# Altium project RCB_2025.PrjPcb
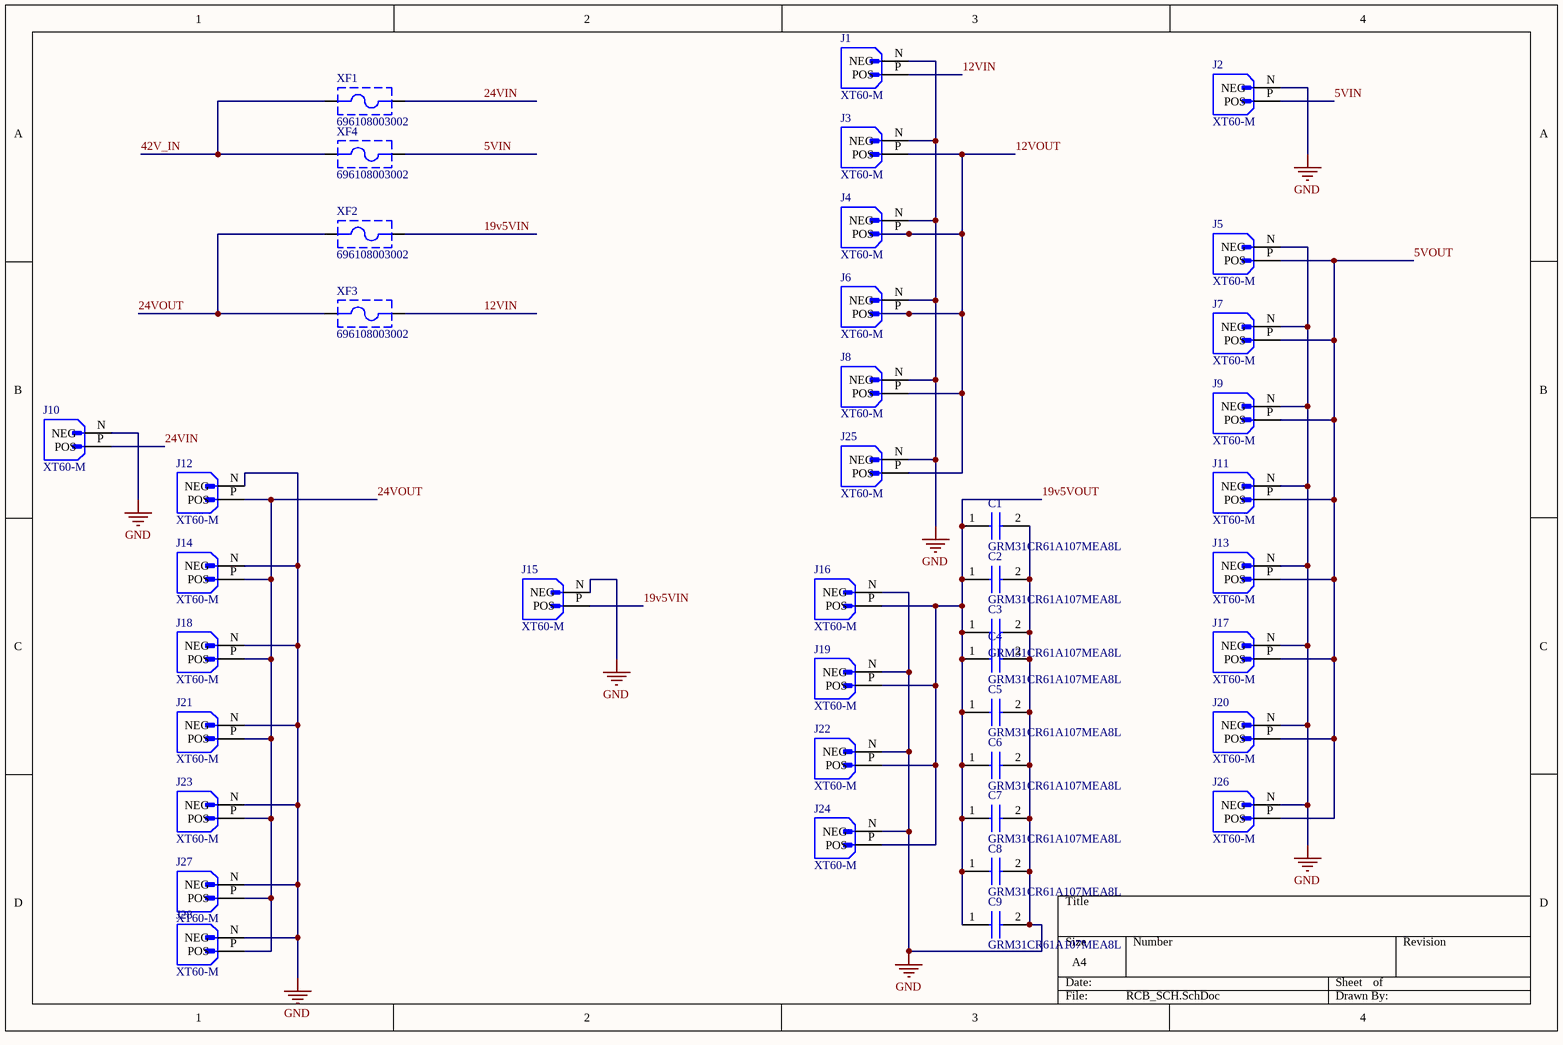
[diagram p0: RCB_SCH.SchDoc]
1 sheet, 41 parts. Net scope: global (net labels, ports and power ports of the same name join across sheets).
Board file: RCB_PCB.PcbDoc

## Sheet RCB_SCH.SchDoc
size A4; SheetNumber: 1; SheetTotal: 1

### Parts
C1  GRM31CR61A107MEA8L  [GRM31x]
C2  GRM31CR61A107MEA8L  [GRM31x]
C3  GRM31CR61A107MEA8L  [GRM31x]
C4  GRM31CR61A107MEA8L  [GRM31x]
C5  GRM31CR61A107MEA8L  [GRM31x]
C6  GRM31CR61A107MEA8L  [GRM31x]
C7  GRM31CR61A107MEA8L  [GRM31x]
C8  GRM31CR61A107MEA8L  [GRM31x]
C9  GRM31CR61A107MEA8L  [GRM31x]
J1  XT60-M  [XT60-M-Footprint-1]
J2  XT60-M  [XT60-M-Footprint-1]
J3  XT60-M  [XT60-M-Footprint-1]
J4  XT60-M  [XT60-M-Footprint-1]
J5  XT60-M  [XT60-M-Footprint-1]
J6  XT60-M  [XT60-M-Footprint-1]
J7  XT60-M  [XT60-M-Footprint-1]
J8  XT60-M  [XT60-M-Footprint-1]
J9  XT60-M  [XT60-M-Footprint-1]
J10  XT60-M  [XT60-M-Footprint-1]
J11  XT60-M  [XT60-M-Footprint-1]
J12  XT60-M  [XT60-M-Footprint-1]
J13  XT60-M  [XT60-M-Footprint-1]
J14  XT60-M  [XT60-M-Footprint-1]
J15  XT60-M  [XT60-M-Footprint-1]
J16  XT60-M  [XT60-M-Footprint-1]
J17  XT60-M  [XT60-M-Footprint-1]
J18  XT60-M  [XT60-M-Footprint-1]
J19  XT60-M  [XT60-M-Footprint-1]
J20  XT60-M  [XT60-M-Footprint-1]
J21  XT60-M  [XT60-M-Footprint-1]
J22  XT60-M  [XT60-M-Footprint-1]
J23  XT60-M  [XT60-M-Footprint-1]
J24  XT60-M  [XT60-M-Footprint-1]
J25  XT60-M  [XT60-M-Footprint-1]
J26  XT60-M  [XT60-M-Footprint-1]
J27  XT60-M  [XT60-M-Footprint-1]
J28  XT60-M  [XT60-M-Footprint-1]
XF1  696108003002  [696108003002]
XF2  696108003002  [696108003002]
XF3  696108003002  [696108003002]
XF4  696108003002  [696108003002]

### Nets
GND: C1.2 C2.2 C3.2 C4.2 C5.2 C6.2 C7.2 C8.2 C9.2 J1.N(NEG) J2.N(NEG) J3.N(NEG) J4.N(NEG) J5.N(NEG) J6.N(NEG) J7.N(NEG) J8.N(NEG) J9.N(NEG) J10.N(NEG) J11.N(NEG) J12.N(NEG) J13.N(NEG) J14.N(NEG) J15.N(NEG) J16.N(NEG) J17.N(NEG) J18.N(NEG) J19.N(NEG) J20.N(NEG) J21.N(NEG) J22.N(NEG) J23.N(NEG) J24.N(NEG) J25.N(NEG) J26.N(NEG) J27.N(NEG) J28.N(NEG)
5VIN: J2.P(POS) XF4.2
5VOUT: J5.P(POS) J7.P(POS) J9.P(POS) J11.P(POS) J13.P(POS) J17.P(POS) J20.P(POS) J26.P(POS)
12VIN: J1.P(POS) XF3.2
12VOUT: J3.P(POS) J4.P(POS) J6.P(POS) J8.P(POS) J25.P(POS)
19v5VIN: J15.P(POS) XF2.2
19v5VOUT: C1.1 C2.1 C3.1 C4.1 C5.1 C6.1 C7.1 C8.1 C9.1 J16.P(POS) J19.P(POS) J22.P(POS) J24.P(POS)
24VIN: J10.P(POS) XF1.2
24VOUT: J12.P(POS) J14.P(POS) J18.P(POS) J21.P(POS) J23.P(POS) J27.P(POS) J28.P(POS) XF2.1 XF3.1
42V_IN: XF1.1 XF4.1

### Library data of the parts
C1-C9 = GRM31CR61A107MEA8L: Capacitor; Manufacturer_Name: Murata Electronics
J1-J28 = CMP-002-00074-2: XT60 Male Connector
XF1-XF4 = CMP-1502-00237-2: NexarPartId: 56808807; Voltage Rating (AC): 250V; Fuse Current: 10A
